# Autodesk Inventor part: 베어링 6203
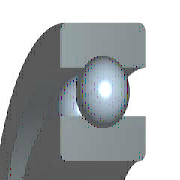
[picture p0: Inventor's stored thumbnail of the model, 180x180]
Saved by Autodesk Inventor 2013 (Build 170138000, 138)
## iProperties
IsCustomPart: 0
Company: 한국ATC센터
Created: 2014-10
Part Number: 베어링 6203
Material: Steel, Mild
Description: 깊은 그루브 볼 베어링
Document SubType Name: Modeling
Standard: KS B 2023
Designer: KYOUNG IL JANG
Standards Organization: KS
Language: ko-KR
Size Designation: 6203 - 17 x 40 x 12
Categories: <MemberInstance><Categories><Category DisplayName="샤프트 부품" InternalName="7f7aeb1f-a693-4053-b835-cee3144e0d98" Mnemonic="SHFT"><Category DisplayName="베어링" Inter
Density: 7.86 g/cm^3
Mass: 64.9809 g
Surface Area: 64.3582 cm^2
Volume: 8.26729 cm^3
Author: KYOUNG IL JANG
Revision Number: 1
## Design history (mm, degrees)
sketch "스케치" dims "d0" = 5.98 (= -0.26 x WD + 0.26 x BD)
  geometry: L1 (3.01, 14.25)-(8.99, 14.25); L2 (6, 14.25)-(6, 11.26); L3 (6, 14.25)-(6, 17.24); L4 (3.778, 12.249)-(0, 12.249); L5 (0, 8.5)-(12, 8.5); L6 (3.778, 16.251)-(0, 16.251); L7 (0, 20)-(12, 20); L8 (12, 8.5)-(12, 12.249); L9 (8.222, 12.249)-(12, 12.249); L10 (8.222, 16.251)-(12, 16.251); L11 (12, 20)-(12, 16.251); L12 (-1.4, 0)-(8.4, 0) reference; L13 (0, -0.3)-(0, 5.3) reference
  constraints: 22 end point, 4 point on line, 2 collinear, 2 perpendicular, 2 symmetric about line, 1 midpoint, 1 parallel, 14 other
  dimensions: "d9" = 17 diameter of L5 L12 (= WD); "d11" = 40 diameter of L7 L12 (= BD); "d12" = 12 distance between parallel lines of L8 L13 (= KB); "d13" = 24.498 diameter of L9 L12 (= 0.326 x BD + 0.674 x WD)
revolve "본체" stored, may be unused: angle "d6" = 90 deg
revolve "볼" stored, may be unused: angle "d7" = 90 deg
pattern_circular "IDS_ARRAYBALL[SIMPL:T]" dims angle "d3" = 360 deg
body "Solid1"
fillet "모깎기1" dims "d1" = 0.6 (= KRS)
other parameters: "WD" = 17 [user parameter; used in 5 equation terms], "BD" = 40 [user parameter; used in 5 equation terms], "KB" = 12 [user parameter; used in 1 equation term], "KRS" = 0.6 [user parameter; used in 1 equation term], "d4" = 0, "d5" = 0, "d8" = 0, "d14" = 0, "d15" = 0, "BBA" = 0 [user parameter], "BC0" = 4750000 [user parameter], "BC" = 9560000 [user parameter], "WR" = 8.5 (= 0.5 x WD) [user parameter]
